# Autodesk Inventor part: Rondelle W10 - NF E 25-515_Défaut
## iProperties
Shininess: 64.0
Length Units: 11269
Angle Units: 11279
Time Units: 11290
Mass Units: 11283
Length Display Precision: 3
Angle Display Precision: 2
Compacted: True
Part Number: Rondelle W10 - NF E 25-515_Défaut
Document SubType Name: Modeling
Created: 2006-01
Material: Par défaut
Designer: riri
Density: 0.0
Volumn: 0.0
Area: 0.0
PropertySet Name: Model Information
Control State: 0
Master: False
Checked Out: False
Author: riri
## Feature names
1. Base1
